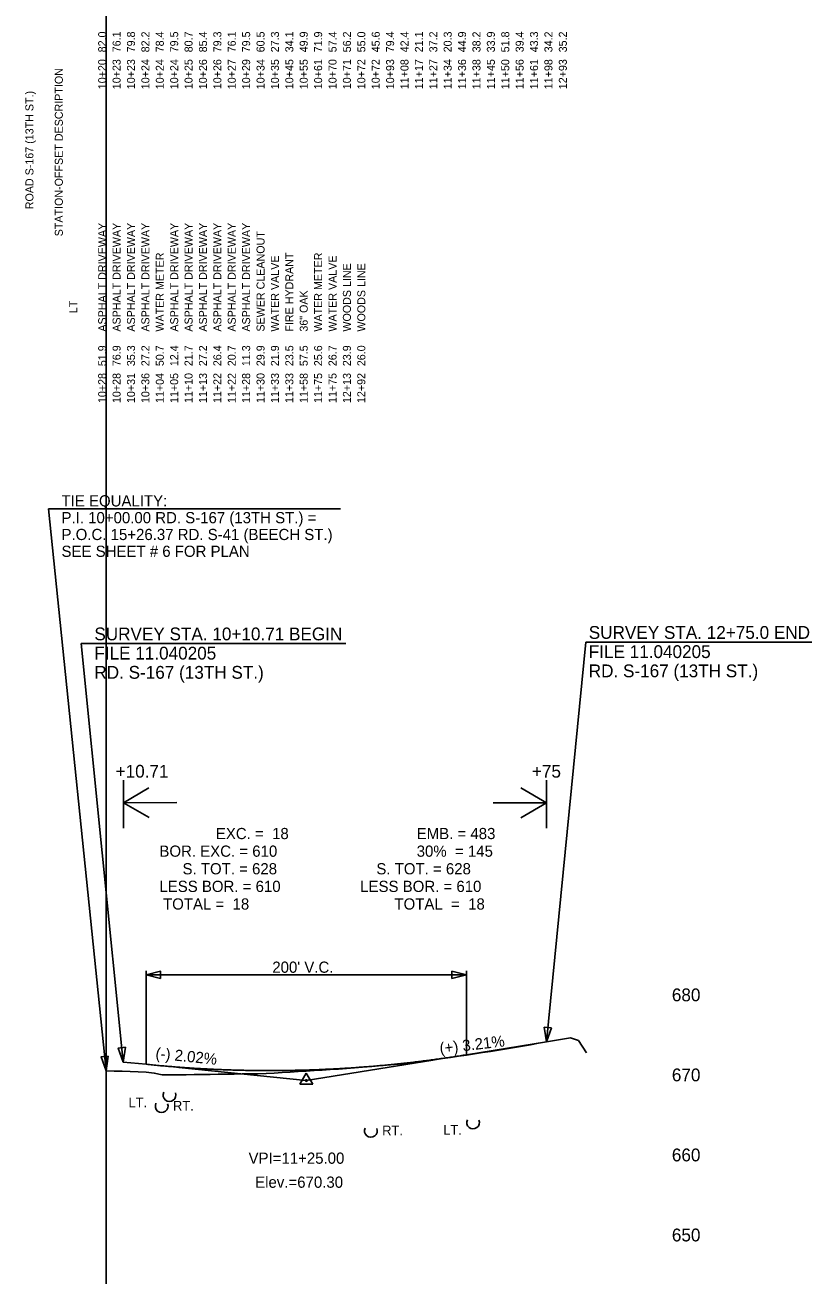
# Model space of a CAD drawing. Extents: x 16382402 to 16388022, y 46194326 to 46202918.
# Drawn here: x 16385126 to 16385617, y 46196901 to 46197682 of the extents above; entities that cross this region are included whole.
import ezdxf

# ---------------------------------------------------------------- set-up
doc = ezdxf.new("R2010")
doc.units = 0
for name, color, linetype in [('Default', 7, 'Continuous'), ('RD_DDB_ElevTX', 7, 'Continuous'), ('RD_DDB_GradeTX', 7, 'Continuous'), ('RD_DDB_Profile_EX', 7, 'Continuous'), ('RD_DDB_Profile_Lbl', 7, 'Continuous'), ('RD_DDB_Profile_PR', 7, 'Continuous'), ('RD_DDB_VCLbl', 7, 'Continuous'), ('RD_GPK_Profile_Cell', 7, 'Continuous'), ('RD_HC_Data', 7, 'Continuous'), ('RD_PD_Final_TX', 7, 'Continuous'), ('RD_TX_Bldg', 7, 'Continuous'), ('RD_TX_Drainage', 7, 'Continuous')]:
    doc.layers.add(name, color=color, linetype=linetype)

msp = doc.modelspace()

# ---------------------------------------------------------------- linework, layer by layer
at = {"layer": 'Default'}
for p, q in [((16385187.06, 46197179.88), (16385187.06, 46197209.88)), ((16385203.08, 46197205.24), (16385187.06, 46197195.8)), ((16385435.25, 46197205.1), (16385451.35, 46197195.8)), ((16385451.35, 46197179.88), (16385451.35, 46197209.88)), ((16385220.39, 46197196.09), (16385187.06, 46197195.8)), ((16385203.24, 46197186.64), (16385187.06, 46197195.8)), ((16385418.02, 46197195.8), (16385451.35, 46197195.8)), ((16385435.25, 46197186.5), (16385451.35, 46197195.8))]:
    msp.add_line(p, q, dxfattribs=at)
for centre in [(16385215.89, 46197013.18), (16385211.01, 46197006.31), (16385341.69, 46196990.88), (16385405.53, 46196996.07)]:
    msp.add_arc(centre, 3.98, 153.82804, 22.53319, dxfattribs=at)
at = {"layer": 'RD_DDB_GradeTX'}
for p in [(16385380.34, 46197034.99), (16385221.76, 46197030.35)]:
    msp.add_line(p, (16385301.35, 46197022.3), dxfattribs=at)
at = {"layer": 'RD_DDB_Profile_EX'}
msp.add_lwpolyline([(16385176.35, 46197028.32), (16385181.35, 46197028.15), (16385186.35, 46197028.08), (16385191.35, 46197027.87), (16385196.35, 46197027.66), (16385201.35, 46197027.45), (16385206.35, 46197026.92), (16385211.35, 46197025.91), (16385216.35, 46197025.81), (16385221.35, 46197025.78), (16385226.35, 46197025.94), (16385231.35, 46197026.04), (16385236.35, 46197026.09), (16385241.35, 46197026.15), (16385246.35, 46197026.21), (16385251.35, 46197026.28), (16385256.35, 46197026.33), (16385261.35, 46197026.39), (16385266.35, 46197026.45), (16385271.35, 46197026.39), (16385276.35, 46197026.59), (16385281.35, 46197026.91), (16385286.35, 46197027.22), (16385291.35, 46197027.54), (16385296.35, 46197027.86), (16385301.35, 46197028.18), (16385306.35, 46197028.5), (16385311.35, 46197028.82), (16385316.35, 46197029.13), (16385321.35, 46197029.46), (16385326.35, 46197029.85), (16385331.35, 46197030.28), (16385336.35, 46197030.7), (16385341.35, 46197031.13), (16385346.35, 46197031.55), (16385351.35, 46197031.95), (16385356.35, 46197032.38), (16385361.35, 46197032.8), (16385366.35, 46197033.22), (16385371.35, 46197033.7), (16385376.35, 46197034.44), (16385381.35, 46197035.2), (16385386.35, 46197035.97), (16385391.35, 46197036.73), (16385396.35, 46197037.48), (16385401.35, 46197038.23), (16385406.35, 46197038.99), (16385411.35, 46197039.76), (16385416.35, 46197040.52), (16385421.35, 46197041.3), (16385426.35, 46197042.15), (16385431.35, 46197043), (16385436.35, 46197043.84), (16385441.35, 46197044.69), (16385446.35, 46197045.54), (16385451.35, 46197046.39), (16385456.35, 46197047.24), (16385461.35, 46197048.09), (16385466.35, 46197048.94), (16385471.35, 46197047.31), (16385476.35, 46197039.66)], dxfattribs=at)
at = {"layer": 'RD_DDB_Profile_PR'}
for p, q in [((16385401.35, 46197038.36), (16385451.35, 46197046.39)), ((16385187.03, 46197033.86), (16385201.35, 46197032.42))]:
    msp.add_line(p, q, dxfattribs=at)
msp.add_spline([(16385201.35, 46197032.42), (16385205.35, 46197032.02), (16385209.35, 46197031.65), (16385213.35, 46197031.3), (16385217.35, 46197030.97), (16385221.35, 46197030.65), (16385225.35, 46197030.37), (16385229.35, 46197030.1), (16385233.35, 46197029.85), (16385237.35, 46197029.62), (16385241.35, 46197029.42), (16385245.35, 46197029.23), (16385249.35, 46197029.07), (16385253.35, 46197028.93), (16385257.35, 46197028.8), (16385261.35, 46197028.7), (16385265.35, 46197028.62), (16385269.35, 46197028.56), (16385273.35, 46197028.53), (16385277.35, 46197028.51), (16385281.35, 46197028.51), (16385285.35, 46197028.54), (16385289.35, 46197028.58), (16385293.35, 46197028.65), (16385297.35, 46197028.74), (16385301.35, 46197028.84), (16385305.35, 46197028.97), (16385309.35, 46197029.12), (16385313.35, 46197029.29), (16385317.35, 46197029.49), (16385321.35, 46197029.7), (16385325.35, 46197029.93), (16385329.35, 46197030.19), (16385333.35, 46197030.47), (16385337.35, 46197030.76), (16385341.35, 46197031.08), (16385345.35, 46197031.42), (16385349.35, 46197031.78), (16385353.35, 46197032.16), (16385357.35, 46197032.56), (16385361.35, 46197032.98), (16385365.35, 46197033.43), (16385369.35, 46197033.89), (16385373.35, 46197034.38), (16385377.35, 46197034.88), (16385381.35, 46197035.41), (16385385.35, 46197035.96), (16385389.35, 46197036.53), (16385393.35, 46197037.12), (16385397.35, 46197037.73), (16385401.35, 46197038.36)], degree=3, dxfattribs=at)
at = {"layer": 'RD_DDB_VCLbl'}
for p, q in [((16385201.35, 46197090.86), (16385201.35, 46197032.42)), ((16385201.35, 46197088.36), (16385401.35, 46197088.36)), ((16385401.35, 46197090.86), (16385401.35, 46197038.36))]:
    msp.add_line(p, q, dxfattribs=at)
at = {"layer": 'RD_GPK_Profile_Cell'}
msp.add_line((16385176.35, 46196770.8), (16385176.35, 46198020.8), dxfattribs=at)
at = {"layer": 'RD_HC_Data'}
for p, q in [((16385140.36, 46197379.52), (16385322.79, 46197379.52)), ((16385176.35, 46197028.32), (16385140.36, 46197379.52)), ((16385297.38, 46197020.01), (16385301.35, 46197026.89)), ((16385301.35, 46197026.89), (16385305.32, 46197020.01)), ((16385297.38, 46197020.01), (16385305.32, 46197020.01))]:
    msp.add_line(p, q, dxfattribs=at)
msp.add_circle((16385301.35, 46197022.3), 0.529, dxfattribs=at)
at = {"layer": 'RD_PD_Final_TX'}
for p, q in [((16385451.35, 46197046.39), (16385475.98, 46197296.21)), ((16385475.98, 46197296.21), (16385617.22, 46197296.21)), ((16385160.69, 46197295.29), (16385326.03, 46197295.29)), ((16385187.03, 46197033.86), (16385160.69, 46197295.29))]:
    msp.add_line(p, q, dxfattribs=at)
at = {"layer": 'RD_TX_Drainage'}
for points in [[(16385210.35, 46197086.11), (16385201.35, 46197088.36), (16385210.35, 46197090.61)], [(16385392.35, 46197090.61), (16385401.35, 46197088.36), (16385392.35, 46197086.11)], [(16385454.47, 46197055.13), (16385451.35, 46197046.39), (16385449.99, 46197055.57)], [(16385188.37, 46197043.05), (16385187.03, 46197033.86), (16385183.89, 46197042.59)], [(16385177.67, 46197037.5), (16385176.35, 46197028.32), (16385173.19, 46197037.04)]]:
    msp.add_lwpolyline(points, close=True, dxfattribs=at)

# ---------------------------------------------------------------- texts
at = {"layer": 'Default'}
for s, height, p in [('+10.71', 8, (16385182.24, 46197211.51)), ('+75', 8, (16385442.26, 46197211.51)), ('EXC. =  18', 7, (16385244.85, 46197173.1)), ('EMB. = 483', 7, (16385370.29, 46197173.1)), ('BOR. EXC. = 610', 7, (16385209.58, 46197162.1)), ('30%  = 145', 7, (16385370.29, 46197162.1)), ('S. TOT. = 628', 7, (16385224.02, 46197151.1)), (' S. TOT. = 628', 7, (16385342.51, 46197151.1)), ('LESS BOR. = 610', 7, (16385209.58, 46197140.1)), ('LESS BOR. = 610', 7, (16385335.01, 46197140.1)), ('      TOTAL =  18', 7, (16385196.24, 46197129.1)), ('TOTAL  =  18', 7, (16385356.4, 46197129.1)), ('LT.', 6, (16385190.27, 46197005.56)), ('RT.', 6, (16385218.09, 46197003.53)), ('RT.', 6, (16385348.77, 46196988.1)), ('LT.', 6, (16385386.94, 46196988.45))]:
    msp.add_text(s, height=height, dxfattribs=at).set_placement(p)
at = {"layer": 'RD_DDB_ElevTX'}
for s, p in [('680', (16385529.69, 46197071.8)), ('670', (16385529.69, 46197021.8)), ('660', (16385529.69, 46196971.8)), ('650', (16385529.69, 46196921.8))]:
    msp.add_text(s, height=8, dxfattribs=at).set_placement(p)
at = {"layer": 'RD_DDB_GradeTX'}
for s, rotation, p in [('(+) 3.21%', 6.75305, (16385385.02, 46197038.87)), ('(-) 2.02%', 354.22342, (16385206.92, 46197035.98))]:
    msp.add_text(s, height=7, rotation=rotation, dxfattribs=at).set_placement(p)
at = {"layer": 'RD_DDB_Profile_Lbl'}
for s, p in [('VPI=11+25.00', (16385265.26, 46196970.3)), ('Elev.=670.30', (16385269.4, 46196955.3))]:
    msp.add_text(s, height=7, dxfattribs=at).set_placement(p)
at = {"layer": 'RD_DDB_VCLbl'}
msp.add_text("200' V.C.", height=7, dxfattribs=at).set_placement((16385280.1, 46197089.61))
at = {"layer": 'RD_HC_Data'}
for s, p in [('TIE EQUALITY:', (16385148.43, 46197380.94)), ('P.I. 10+00.00 RD. S-167 (13TH ST.) =', (16385148.43, 46197370.44)), ('P.O.C. 15+26.37 RD. S-41 (BEECH ST.)', (16385148.43, 46197359.94)), ('SEE SHEET # 6 FOR PLAN', (16385148.43, 46197349.44))]:
    msp.add_text(s, height=7, dxfattribs=at).set_placement(p)
at = {"layer": 'RD_PD_Final_TX'}
for s, p in [('SURVEY STA. 10+10.71 BEGIN', (16385168.95, 46197297.3)), ('SURVEY STA. 12+75.0 END', (16385477.77, 46197298.23)), ('FILE 11.040205', (16385168.95, 46197285.3)), ('FILE 11.040205', (16385477.77, 46197286.23)), ('RD. S-167 (13TH ST.)', (16385168.95, 46197273.3)), ('RD. S-167 (13TH ST.)', (16385477.77, 46197274.23))]:
    msp.add_text(s, height=8, dxfattribs=at).set_placement(p)
at = {"layer": 'RD_TX_Bldg'}
for s, p in [('82.0', (16385176.35, 46197664.65)), ('76.1', (16385185.34, 46197664.65)), ('79.8', (16385194.33, 46197664.65)), ('82.2', (16385203.33, 46197664.65)), ('78.4', (16385212.32, 46197664.65)), ('79.5', (16385221.31, 46197664.65)), ('80.7', (16385230.3, 46197664.65)), ('85.4', (16385239.29, 46197664.65)), ('79.3', (16385248.28, 46197664.65)), ('76.1', (16385257.28, 46197664.65)), ('79.5', (16385266.27, 46197664.65)), ('60.5', (16385275.26, 46197664.65)), ('27.3', (16385284.25, 46197664.65)), ('34.1', (16385293.24, 46197664.65)), ('49.9', (16385302.23, 46197664.65)), ('71.9', (16385311.23, 46197664.65)), ('57.4', (16385320.22, 46197664.65)), ('56.2', (16385329.21, 46197664.65)), ('55.0', (16385338.2, 46197664.65)), ('45.6', (16385347.19, 46197664.65)), ('79.4', (16385356.19, 46197664.65)), ('42.4', (16385365.18, 46197664.65)), ('21.1', (16385374.17, 46197664.65)), ('37.2', (16385383.16, 46197664.65)), ('20.3', (16385392.15, 46197664.65)), ('44.9', (16385401.14, 46197664.65)), ('38.2', (16385410.14, 46197664.65)), ('33.9', (16385419.13, 46197664.65)), ('51.8', (16385428.12, 46197664.65)), ('39.4', (16385437.11, 46197664.65)), ('43.3', (16385446.1, 46197664.65)), ('34.2', (16385455.09, 46197664.65)), ('35.2', (16385464.09, 46197664.65)), ('10+20', (16385176.35, 46197641.6)), ('10+23', (16385185.34, 46197641.6)), ('10+23', (16385194.33, 46197641.6)), ('10+24', (16385203.33, 46197641.6)), ('10+24', (16385212.32, 46197641.6)), ('10+24', (16385221.31, 46197641.6)), ('10+25', (16385230.3, 46197641.6)), ('10+26', (16385239.29, 46197641.6)), ('10+26', (16385248.28, 46197641.6)), ('10+27', (16385257.28, 46197641.6)), ('10+29', (16385266.27, 46197641.6)), ('10+34', (16385275.26, 46197641.6)), ('10+35', (16385284.25, 46197641.6)), ('10+45', (16385293.24, 46197641.6)), ('10+55', (16385302.23, 46197641.6)), ('10+61', (16385311.23, 46197641.6)), ('10+70', (16385320.22, 46197641.6)), ('10+71', (16385329.21, 46197641.6)), ('10+72', (16385338.2, 46197641.6)), ('10+72', (16385347.19, 46197641.6)), ('10+93', (16385356.19, 46197641.6)), ('11+08', (16385365.18, 46197641.6)), ('11+17', (16385374.17, 46197641.6)), ('11+27', (16385383.16, 46197641.6)), ('11+34', (16385392.15, 46197641.6)), ('11+36', (16385401.14, 46197641.6)), ('11+38', (16385410.14, 46197641.6)), ('11+45', (16385419.13, 46197641.6)), ('11+50', (16385428.12, 46197641.6)), ('11+56', (16385437.11, 46197641.6)), ('11+61', (16385446.1, 46197641.6)), ('11+98', (16385455.09, 46197641.6)), ('12+93', (16385464.09, 46197641.6)), ('STATION-OFFSET DESCRIPTION', (16385149.25, 46197549.7)), ('ROAD S-167 (13TH ST.)', (16385130.89, 46197566.61)), ('ASPHALT DRIVEWAY', (16385176.35, 46197490.16)), ('ASPHALT DRIVEWAY', (16385185.34, 46197490.16)), ('ASPHALT DRIVEWAY', (16385194.33, 46197490.16)), ('ASPHALT DRIVEWAY', (16385203.33, 46197490.16)), ('ASPHALT DRIVEWAY', (16385221.31, 46197490.16)), ('ASPHALT DRIVEWAY', (16385230.3, 46197490.16)), ('ASPHALT DRIVEWAY', (16385239.29, 46197490.16)), ('ASPHALT DRIVEWAY', (16385248.28, 46197490.16)), ('ASPHALT DRIVEWAY', (16385257.28, 46197490.16)), ('ASPHALT DRIVEWAY', (16385266.27, 46197490.16)), ('SEWER CLEANOUT', (16385275.26, 46197490.16)), ('WATER METER', (16385212.32, 46197490.16)), ('FIRE HYDRANT', (16385293.24, 46197490.16)), ('WATER METER', (16385311.23, 46197490.16)), ('WATER VALVE', (16385284.25, 46197490.16)), ('WATER VALVE', (16385320.22, 46197490.16)), ('WOODS LINE', (16385329.21, 46197490.16)), ('WOODS LINE', (16385338.2, 46197490.16)), ('36" OAK', (16385302.23, 46197490.16)), ('LT', (16385158.24, 46197501.67)), ('51.9', (16385176.35, 46197468.58)), ('76.9', (16385185.34, 46197468.58)), ('35.3', (16385194.33, 46197468.58)), ('27.2', (16385203.33, 46197468.58)), ('50.7', (16385212.32, 46197468.58)), ('12.4', (16385221.31, 46197468.58)), ('21.7', (16385230.3, 46197468.58)), ('27.2', (16385239.29, 46197468.58)), ('26.4', (16385248.28, 46197468.58)), ('20.7', (16385257.28, 46197468.58)), ('11.3', (16385266.27, 46197468.58)), ('29.9', (16385275.26, 46197468.58)), ('21.9', (16385284.25, 46197468.58)), ('23.5', (16385293.24, 46197468.58)), ('57.5', (16385302.23, 46197468.58)), ('25.6', (16385311.23, 46197468.58)), ('26.7', (16385320.22, 46197468.58)), ('23.9', (16385329.21, 46197468.58)), ('26.0', (16385338.2, 46197468.58)), ('10+28', (16385176.35, 46197445.53)), ('10+28', (16385185.34, 46197445.53)), ('10+31', (16385194.33, 46197445.53)), ('10+36', (16385203.33, 46197445.53)), ('11+04', (16385212.32, 46197445.53)), ('11+05', (16385221.31, 46197445.53)), ('11+10', (16385230.3, 46197445.53)), ('11+13', (16385239.29, 46197445.53)), ('11+22', (16385248.28, 46197445.53)), ('11+22', (16385257.28, 46197445.53)), ('11+28', (16385266.27, 46197445.53)), ('11+30', (16385275.26, 46197445.53)), ('11+33', (16385284.25, 46197445.53)), ('11+33', (16385293.24, 46197445.53)), ('11+58', (16385302.23, 46197445.53)), ('11+75', (16385311.23, 46197445.53)), ('11+75', (16385320.22, 46197445.53)), ('12+13', (16385329.21, 46197445.53)), ('12+92', (16385338.2, 46197445.53))]:
    msp.add_text(s, height=5, rotation=90, dxfattribs=at).set_placement(p)

doc.saveas('drawing.dxf')
